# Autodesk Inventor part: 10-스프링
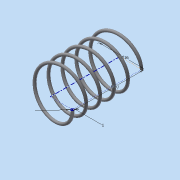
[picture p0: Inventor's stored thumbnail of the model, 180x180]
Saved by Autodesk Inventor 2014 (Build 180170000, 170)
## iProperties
Created: 2015-06
Part Number: 10-스프링
Material: 강철, 연강
Document SubType Name: Modeling
Designer: MYHOME
Density: 7.86 g/cm^3
Appearance: 강철
Mass: 1.52988 g
Surface Area: 7.87024 cm^2
Volume: 0.194641 cm^3
Author: MYHOME
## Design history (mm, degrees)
sketch "스케치1"
  geometry: L1 (0, 0)-(8, 0); L2 (8, 0)-(8, 14.5); L3 (8, 14.5)-(0, 14.5); L4 (0, 14.5)-(0, 0); C1 r 0.5 at (8, 0)
  constraints: 8 end point, 2 parallel, 1 centre point, 1 coincident, 1 horizontal, 1 perpendicular
  dimensions: "d0" = 1 diameter of C1; "d1" = 16 diameter of L2 L4; "d2" = 14.5 distance of L1.end L2.end (derived)
feature "코일1" sketch "스케치1" pitch "d3" = 10; turns "d5" = 5; dims "d4" = 14.5 (= d2), "d6" = 0, angle "d7" = 90 deg, angle "d8" = 90 deg, "d9" = 0, "d10" = 0
sketch "스케치2"
  geometry: L1 (-8.5, 0)-(-7.5, 0) reference; 1 further point
  constraints: 1 horizontal alignment
extrude "돌출1" cut sketch "스케치2" stored distance "d11" = 10; taper "d12" = 0 deg
node "작업 평면1"
sketch "스케치3"
  geometry: L1 (-7.5, 0)-(-8.5, 0) reference; 1 further point
  constraints: 1 horizontal alignment
extrude "돌출2" cut sketch "스케치3" stored distance "d14" = 10; taper "d15" = 0 deg
node "솔리드1"
node "절단 모서리 투영1"
node "절단 모서리 투영2"
other parameters: "d13" = 14.5 (= d2)
